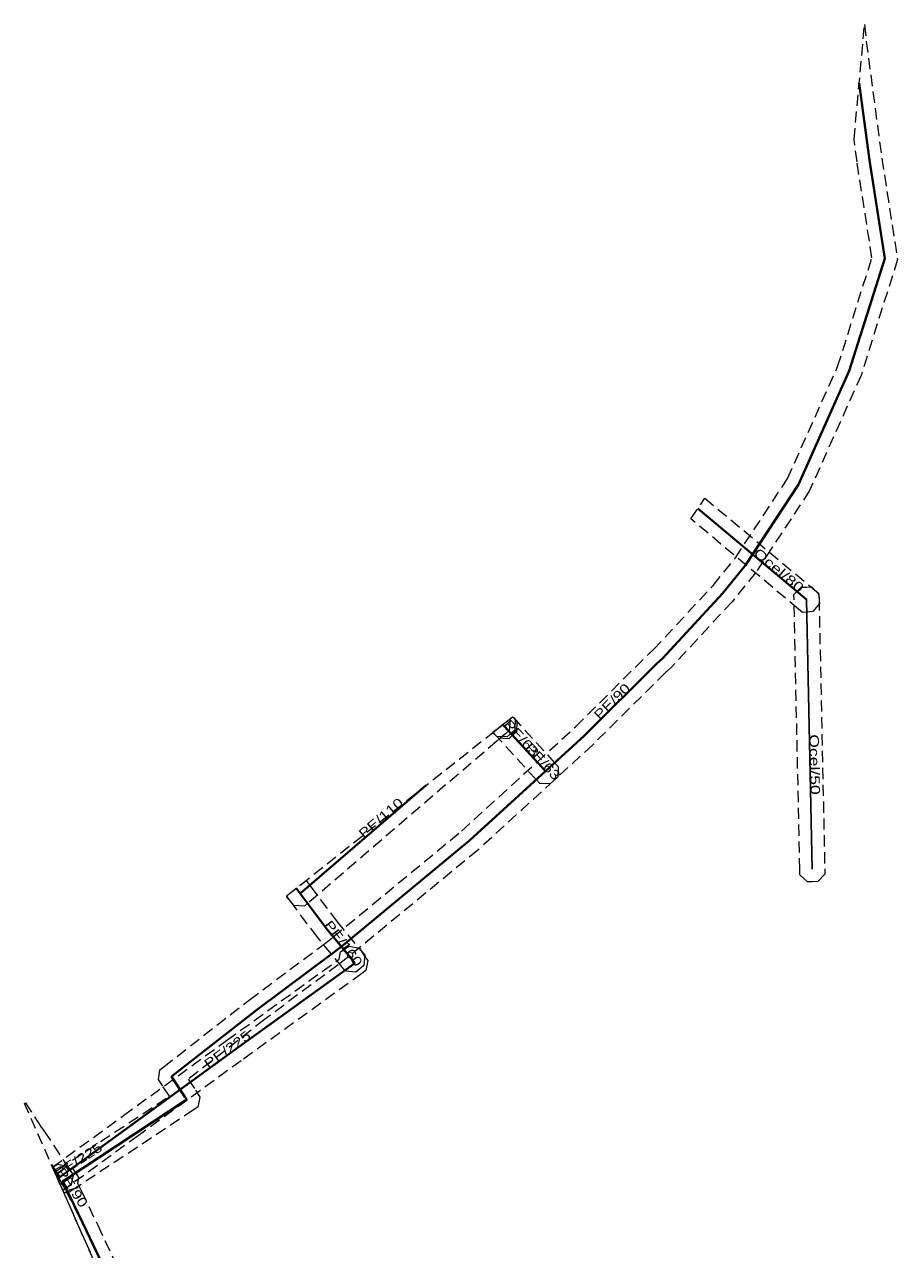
# Model space of a CAD drawing. Extents: x -469725 to -469636, y -1098908 to -1098712.
# Drawn here: x -469724.6 to -469654.7, y -1098809.9 to -1098711.8 of the extents above; entities that cross this region are included whole.
import ezdxf

# ---------------------------------------------------------------- set-up
doc = ezdxf.new("R2010")
doc.units = 0
doc.header["$LTSCALE"] = 0.3
doc.linetypes.add('MEDIUM_DASHED', pattern=[4.5, 3, -1.5])
for name, color, linetype, lineweight in [('1', 7, 'MEDIUM_DASHED', 13), ('14', 7, 'Continuous', 40), ('24', 7, 'Continuous', 40)]:
    doc.layers.add(name, color=color, linetype=linetype, lineweight=lineweight)
doc.layers.add('20', color=7, linetype='Continuous')
doc.layers.add('30', color=7, linetype='Continuous')

msp = doc.modelspace()

# ---------------------------------------------------------------- linework, layer by layer
at = {"layer": '1'}
for points in [[(-469721.499, -1098805.333), (-469722.221, -1098803.699), (-469721.928, -1098803.504), (-469713.036, -1098797.622), (-469713.562, -1098796.829), (-469713.703, -1098796.618), (-469713.92, -1098796.292), (-469713.795, -1098795.518), (-469713.486, -1098795.277), (-469706.637, -1098789.915), (-469700.73, -1098785.511), (-469699.918, -1098784.885), (-469689.655, -1098776.415), (-469683.602, -1098770.874), (-469680.52, -1098768.054), (-469674.7, -1098762.265), (-469674.27, -1098761.874), (-469669.495, -1098756.727), (-469667.716, -1098754.533), (-469663.539, -1098748.177), (-469659.529, -1098739.204), (-469656.784, -1098730.488), (-469657.975, -1098722.815), (-469658.212, -1098721.021), (-469657.376, -1098711.816), (-469657.234, -1098713.174), (-469655.995, -1098722.531), (-469654.736, -1098730.644), (-469657.657, -1098739.914), (-469661.779, -1098749.141), (-469666.1, -1098755.715), (-469667.983, -1098758.039), (-469672.862, -1098763.298), (-469673.322, -1098763.715), (-469679.14, -1098769.502), (-469682.252, -1098772.35), (-469688.343, -1098777.925), (-469698.67, -1098786.449), (-469699.522, -1098787.105), (-469705.423, -1098791.505), (-469711.526, -1098796.281), (-469710.956, -1098797.14), (-469710.816, -1098797.353), (-469710.588, -1098797.699), (-469710.753, -1098798.51), (-469711.098, -1098798.738), (-469720.824, -1098805.172), (-469721.169, -1098805.401)], [(-469662.662, -1098758.631), (-469671.279, -1098751.41), (-469670.151, -1098749.746), (-469661.378, -1098757.099), (-469661.06, -1098757.365), (-469660.988, -1098758.19), (-469661.254, -1098758.507), (-469661.52, -1098758.825), (-469662.345, -1098758.897)], [(-469661.029, -1098757.43), (-469661.02, -1098757.844), (-469660.559, -1098779.44), (-469660.55, -1098779.854), (-469661.124, -1098780.452), (-469661.538, -1098780.461), (-469661.952, -1098780.47), (-469662.55, -1098779.896), (-469662.559, -1098779.482), (-469663.02, -1098757.886), (-469663.029, -1098757.472), (-469662.455, -1098756.874), (-469662.041, -1098756.865), (-469661.627, -1098756.856)], [(-469703.596, -1098781.737), (-469703.58, -1098781.534), (-469685.814, -1098767.455), (-469685.758, -1098767.522), (-469685.825, -1098768.343), (-469686.138, -1098768.611), (-469686.363, -1098768.804), (-469686.514, -1098768.935), (-469686.82, -1098769.196), (-469701.916, -1098782.159), (-469702.23, -1098782.429), (-469703.056, -1098782.365), (-469703.326, -1098782.051)], [(-469687.129, -1098768.497), (-469685.557, -1098767.251), (-469685.494, -1098767.32), (-469682.189, -1098770.937), (-469681.909, -1098771.243), (-469681.946, -1098772.071), (-469682.252, -1098772.35), (-469682.558, -1098772.63), (-469683.386, -1098772.593), (-469683.665, -1098772.287), (-469686.97, -1098768.67)], [(-469687.128, -1098768.497), (-469685.557, -1098767.251), (-469685.349, -1098767.478), (-469685.386, -1098768.305), (-469685.692, -1098768.585), (-469685.998, -1098768.865), (-469686.825, -1098768.828), (-469687.105, -1098768.522)], [(-469687.128, -1098768.496), (-469685.557, -1098767.251), (-469685.493, -1098767.321), (-469685.214, -1098767.627), (-469685.252, -1098768.455), (-469685.558, -1098768.734), (-469685.864, -1098769.013), (-469686.692, -1098768.975), (-469686.971, -1098768.669), (-469687.106, -1098768.521)], [(-469703.367, -1098782), (-469703.666, -1098781.602), (-469702.098, -1098780.359), (-469701.767, -1098780.8), (-469699.614, -1098783.671), (-469697.66, -1098786.032), (-469697.396, -1098786.351), (-469697.473, -1098787.176), (-469697.792, -1098787.44), (-469698.111, -1098787.704), (-469698.936, -1098787.627), (-469699.2, -1098787.308), (-469701.186, -1098784.909)], [(-469721.566, -1098805.182), (-469722.391, -1098803.316), (-469716.709, -1098799.182), (-469708.457, -1098793.171), (-469699.448, -1098786.66), (-469699.33, -1098786.068), (-469698.985, -1098785.838), (-469698.64, -1098785.608), (-469697.828, -1098785.77), (-469697.598, -1098786.115), (-469697.378, -1098786.445), (-469697.154, -1098786.781), (-469697.297, -1098787.575), (-469697.624, -1098787.811), (-469707.283, -1098794.789), (-469715.531, -1098800.798), (-469721.222, -1098804.939), (-469721.557, -1098805.183)], [(-469721.257, -1098804.963), (-469721.571, -1098805.171), (-469724.641, -1098798.223), (-469724.563, -1098798.161), (-469723.353, -1098800.027), (-469723.056, -1098800.443), (-469720.977, -1098803.577), (-469720.748, -1098803.922), (-469720.912, -1098804.734)], [(-469721.574, -1098805.163), (-469722.391, -1098803.315), (-469722.344, -1098803.285), (-469721.994, -1098803.064), (-469721.186, -1098803.246), (-469720.965, -1098803.596), (-469720.744, -1098803.946), (-469720.926, -1098804.754), (-469721.276, -1098804.975)], [(-469721.696, -1098804.533), (-469721.747, -1098804.773), (-469722.161, -1098803.835), (-469722.147, -1098803.838), (-469721.921, -1098804.185)]]:
    msp.add_lwpolyline(points, close=True, dxfattribs=at)
for points in [[(-469711.996, -1098826.84), (-469722.222, -1098803.699), (-469722.136, -1098803.642), (-469721.927, -1098803.504), (-469721.582, -1098803.275), (-469720.77, -1098803.441), (-469720.542, -1098803.787), (-469720.313, -1098804.132), (-469720.407, -1098804.59), (-469720.073, -1098805.252), (-469718.782, -1098807.973), (-469714.401, -1098817.204)], [(-469687.178, -1098883.009), (-469722.152, -1098803.856), (-469722.104, -1098803.869), (-469721.896, -1098804.227), (-469721.351, -1098805.163), (-469719.879, -1098808.085), (-469715.384, -1098817.796)]]:
    msp.add_lwpolyline(points, dxfattribs=at)
at = {"layer": '14'}
for p, q in [((-469670.715, -1098750.578), (-469662.02, -1098757.865)), ((-469702.567, -1098781.4), (-469692.466, -1098772.727))]:
    msp.add_line(p, q, dxfattribs=at)
at = {"layer": '14', "lineweight": 25}
msp.add_line((-469662.02, -1098757.865), (-469661.559, -1098779.461), dxfattribs=at)
at = {"layer": '14'}
for points in [[(-469702.882, -1098780.98), (-469702.567, -1098781.4), (-469700.4, -1098784.29), (-469698.43, -1098786.67)], [(-469698.43, -1098786.67), (-469698.21, -1098787), (-469707.87, -1098793.98), (-469716.12, -1098799.99), (-469721.81, -1098804.13)], [(-469722.472, -1098803.133), (-469721.81, -1098804.13), (-469721.983, -1098804.239)]]:
    msp.add_lwpolyline(points, dxfattribs=at)
at = {"layer": '24'}
for points in [[(-469721.376, -1098804.338), (-469711.65, -1098797.904), (-469711.79, -1098797.692), (-469712.729, -1098796.276), (-469712.87, -1098796.064), (-469706.03, -1098790.71), (-469700.126, -1098786.308), (-469699.294, -1098785.667), (-469688.999, -1098777.17), (-469682.927, -1098771.612), (-469679.83, -1098768.778), (-469674.011, -1098762.99), (-469673.565, -1098762.585), (-469668.739, -1098757.383), (-469666.908, -1098755.124), (-469662.659, -1098748.659), (-469658.593, -1098739.559), (-469655.76, -1098730.566), (-469656.985, -1098722.673), (-469657.802, -1098716.504)], [(-469682.927, -1098771.612), (-469686.232, -1098767.995), (-469686.343, -1098767.874)], [(-469674.418, -1098904.68), (-469674.525, -1098904.218), (-469675.85, -1098901.282), (-469680.237, -1098891.753), (-469686.044, -1098879.696), (-469691.984, -1098867.115), (-469697.866, -1098854.442), (-469703.721, -1098842.244), (-469709.506, -1098829.718), (-469710.849, -1098826.917), (-469715.304, -1098817.635), (-469719.685, -1098808.402), (-469720.971, -1098805.692), (-469721.585, -1098804.476), (-469721.376, -1098804.338)]]:
    msp.add_lwpolyline(points, dxfattribs=at)

# ---------------------------------------------------------------- texts
at = {"layer": '20'}
for s, rotation, width, p in [('Ocel/80', 320.034, 1.4, (-469666.329, -1098754.253)), ('Ocel/50', 271.223, 1.4, (-469661.789, -1098768.663)), ('PE/110', 40.653, 1.3, (-469697.479, -1098777.031)), ('PE/160', 306.864, 1.3, (-469700.684, -1098783.911)), ('PE/225', 36.073, 1.3, (-469709.903, -1098795.46)), ('PE/225', 32.276, 1.3, (-469721.939, -1098804.211)), ('PE/90', 303.563, 1.3, (-469722.113, -1098803.673))]:
    msp.add_text(s, height=0.75, rotation=rotation, dxfattribs=dict(at, width=width)).set_placement(p)
at = {"layer": '30', "width": 1.3}
for s, rotation, p in [('PE/90', 44.847, (-469678.587, -1098767.541)), ('PE/63', 312.37, (-469686.321, -1098767.897)), ('PE/63', 312.419, (-469684.613, -1098769.766))]:
    msp.add_text(s, height=0.75, rotation=rotation, dxfattribs=at).set_placement(p)

doc.saveas('drawing.dxf')
